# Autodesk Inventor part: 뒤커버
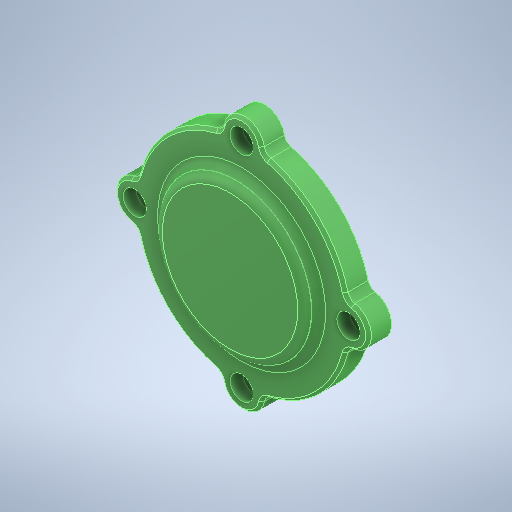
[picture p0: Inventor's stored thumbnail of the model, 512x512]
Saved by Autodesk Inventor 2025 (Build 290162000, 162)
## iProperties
Created: 2024-08
Part Number: 뒤커버
Material: 알루미늄 6061
Document SubType Name: Modeling
Designer: onair
Density: 2.71 g/cm^3
Appearance: 기본값
Company: 한국ATC센터
Author: jhkim
Sending System: Autodesk Inventor 2025
Preprocessor: ST-DEVELOPER v20
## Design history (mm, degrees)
feature "솔리드1"
node "솔리드2"
